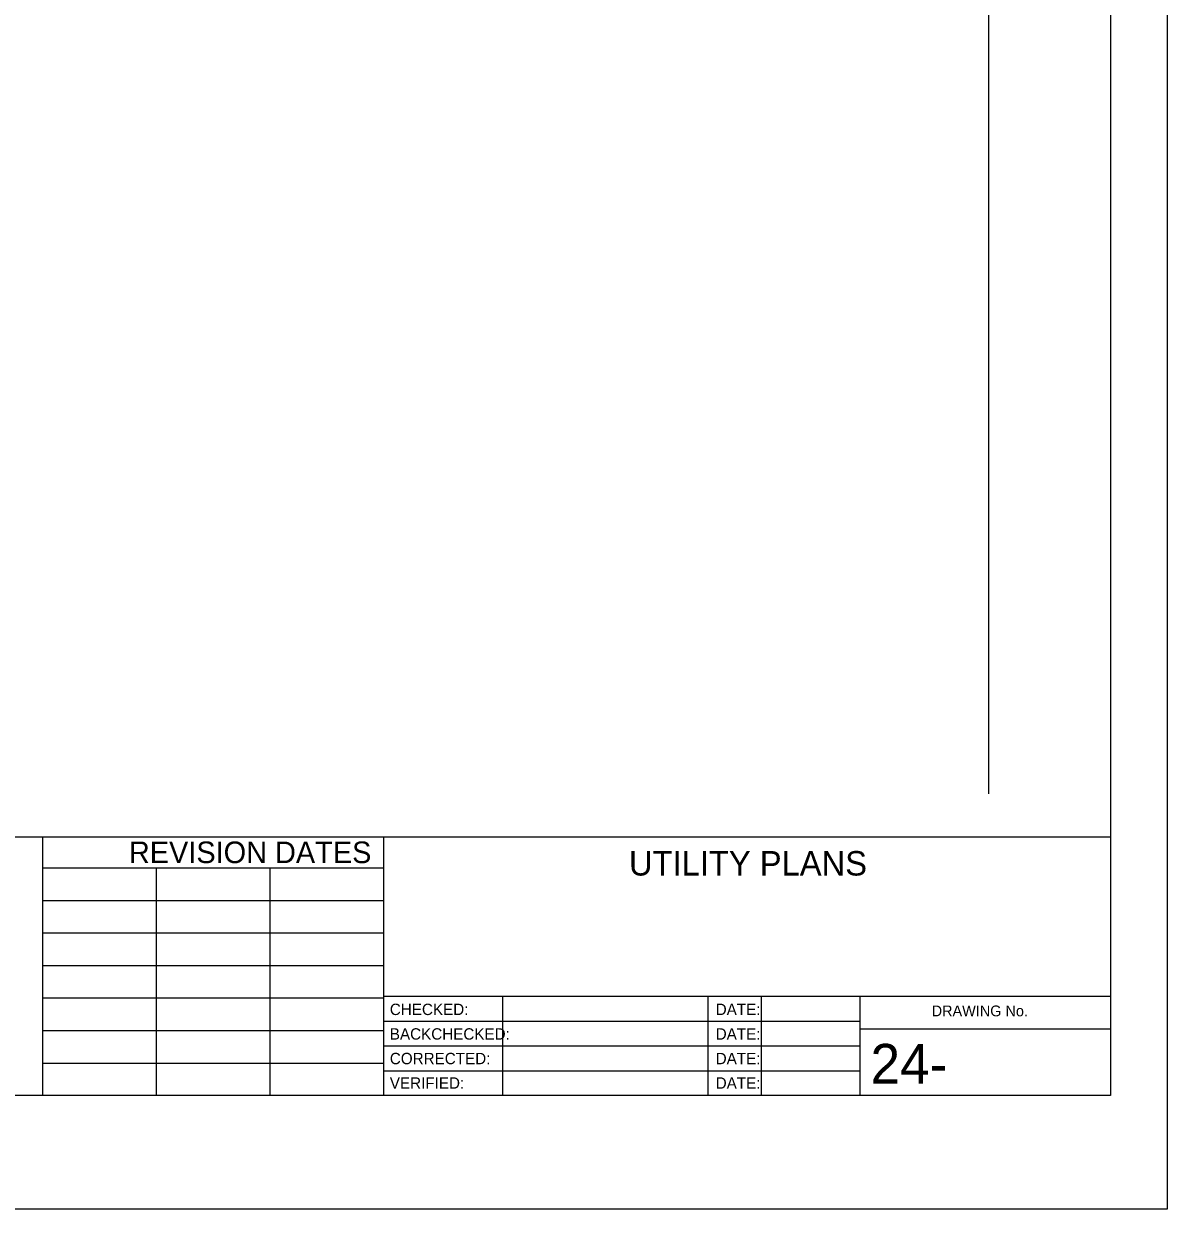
# Model space of a CAD drawing. Extents: x 2157704 to 2158404, y 1040586 to 1041166.
# Drawn here: x 2158202.9 to 2158404, y 1040652.1 to 1040860.6 of the extents above; entities that cross this region are included whole.
import ezdxf

# ---------------------------------------------------------------- set-up
doc = ezdxf.new("R2010")
doc.units = 0
for name, color, linetype in [('SHT_B_20-Staging-Details', 7, 'Continuous'), ('SHT_B_MainLine-Text', 7, 'Continuous'), ('SHT_B_North-Arrow', 7, 'Continuous'), ('SHT_B_Plot-Sub-Text', 7, 'Continuous'), ('UTLE_E_UG-Wat-Line-30-Qual-B-50', 7, 'Continuous'), ('UTLE_E_UG-Wat-Line-30-Qual-C-50', 7, 'Continuous')]:
    doc.layers.add(name, color=color, linetype=linetype)

msp = doc.modelspace()

# ---------------------------------------------------------------- linework, layer by layer
at = {"layer": 'SHT_B_MainLine-Text'}
msp.add_line((2158372.56, 1041070), (2158372.56, 1040725.2), dxfattribs=at)
at = {"layer": 'SHT_B_North-Arrow'}
for p, q in [((2157773.99, 1040717.65), (2158393.99, 1040717.65)), ((2158206.25, 1040672.15), (2158206.25, 1040717.65)), ((2158266.25, 1040672.15), (2158266.25, 1040717.65)), ((2158383.99, 1040717.65), (2158383.99, 1040717.65)), ((2158383.99, 1040717.65), (2158383.99, 1040717.65)), ((2158206.25, 1040712.15), (2158266.25, 1040712.15)), ((2158226.25, 1040672.15), (2158226.25, 1040712.15)), ((2158246.25, 1040672.15), (2158246.25, 1040712.15)), ((2158206.25, 1040706.43), (2158266.25, 1040706.43)), ((2158206.25, 1040700.72), (2158266.25, 1040700.72)), ((2158206.25, 1040695), (2158266.25, 1040695)), ((2158266.25, 1040689.59), (2158393.99, 1040689.59)), ((2158287.18, 1040672.15), (2158287.18, 1040689.59)), ((2158323.26, 1040672.15), (2158323.26, 1040689.59)), ((2158332.64, 1040672.15), (2158332.64, 1040689.59)), ((2158349.99, 1040672.15), (2158349.99, 1040689.59)), ((2158206.25, 1040689.29), (2158266.25, 1040689.29)), ((2158206.25, 1040683.57), (2158266.25, 1040683.57)), ((2158266.25, 1040685.23), (2158349.99, 1040685.23)), ((2158349.99, 1040683.86), (2158393.99, 1040683.86)), ((2158266.25, 1040680.87), (2158349.99, 1040680.87)), ((2158206.25, 1040677.86), (2158266.25, 1040677.86)), ((2158266.25, 1040676.51), (2158349.99, 1040676.51))]:
    msp.add_line(p, q, dxfattribs=at)
at = {"layer": 'SHT_B_Plot-Sub-Text'}
msp.add_line((2158393.99, 1040672.15), (2158393.99, 1040672.15), dxfattribs=at)
at = {"layer": 'UTLE_E_UG-Wat-Line-30-Qual-B-50'}
msp.add_lwpolyline([(2157733.99, 1041092.15), (2158393.99, 1041092.15), (2158393.99, 1040672.15), (2157733.99, 1040672.15)], close=True, dxfattribs=at)
at = {"layer": 'UTLE_E_UG-Wat-Line-30-Qual-C-50'}
msp.add_lwpolyline([(2157703.99, 1041112.15), (2158403.99, 1041112.15), (2158403.99, 1040652.15), (2157703.99, 1040652.15)], close=True, dxfattribs=at)

# ---------------------------------------------------------------- texts
at = {"layer": 'SHT_B_20-Staging-Details'}
for s, height, rotation, p in [('UTILITY PLANS', 4.3, 360, (2158309.33, 1040710.82)), ('24-       ', 7, 0, (2158351.8, 1040674.22))]:
    msp.add_text(s, height=height, rotation=rotation, dxfattribs=at).set_placement(p)
at = {"layer": 'SHT_B_Plot-Sub-Text'}
for s, height, rotation, p in [('REVISION DATES', 3.7999, 0, (2158221.4, 1040713)), ('CHECKED:', 2, 360, (2158267.28, 1040686.29)), ('DATE:', 2, 360, (2158324.58, 1040686.29)), ('DRAWING No.', 1.898, 0, (2158362.56, 1040686.07)), ('BACKCHECKED:', 2, 360, (2158267.28, 1040681.97)), ('DATE:', 2, 360, (2158324.58, 1040681.97)), ('CORRECTED:', 2, 360, (2158267.28, 1040677.65)), ('DATE:', 2, 360, (2158324.58, 1040677.65)), ('VERIFIED:', 2, 360, (2158267.28, 1040673.34)), ('DATE:', 2, 360, (2158324.58, 1040673.34))]:
    msp.add_text(s, height=height, rotation=rotation, dxfattribs=at).set_placement(p)

doc.saveas('drawing.dxf')
